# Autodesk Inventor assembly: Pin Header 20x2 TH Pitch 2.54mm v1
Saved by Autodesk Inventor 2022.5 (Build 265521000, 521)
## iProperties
Created: 2024-12
Part Number: Pin Header 20x2 TH Pitch 2.54mm v1
Document SubType Name: Assembly
Designer: AdminForWorker
Title: Pin Header 20x2 TH Pitch 2.54mm v1
Author: AdminForWorker
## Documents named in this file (3)
- c:\worker\convert-fusion-r05-cosv3\tmp\job-1\35\temp\files\545dca92-a972-481a-9197-dd1a1176500e\Pin Header 20x2 TH Pitch 2.54mm v1.iam
- c:\worker\convert-fusion-r05-cosv3\tmp\job-1\35\temp\files\545dca92-a972-481a-9197-dd1a1176500e\pins.ipt
- c:\worker\convert-fusion-r05-cosv3\tmp\job-1\35\temp\files\545dca92-a972-481a-9197-dd1a1176500e\spacers.iam
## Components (2 placed, 2 different names)
1. pins:1
2. spacers:1 [sub-assembly]
